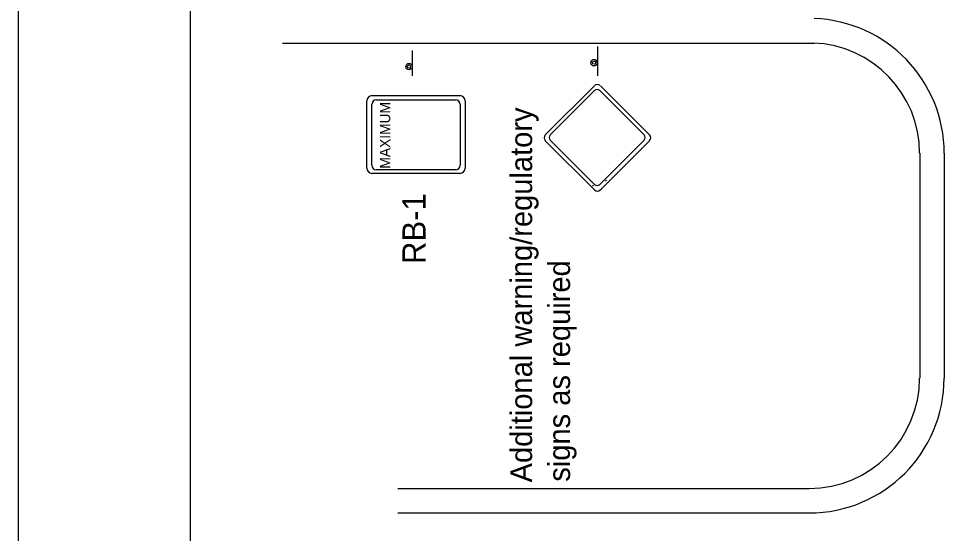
# Model space of a CAD drawing. Extents: x 2111 to 2327, y 208 to 487.
# Drawn here: x 2111.3 to 2214.3, y 349.6 to 406.9 of the extents above; entities that cross this region are included whole.
import ezdxf

# ---------------------------------------------------------------- set-up
doc = ezdxf.new("R2010")
doc.units = 0
for name, color, linetype in [('Level 10', 7, 'Continuous'), ('Level 2', 7, 'Continuous'), ('Level 44', 7, 'Continuous'), ('Level 60', 7, 'Continuous')]:
    doc.layers.add(name, color=color, linetype=linetype)

msp = doc.modelspace()

# ---------------------------------------------------------------- linework, layer by layer
at = {"layer": 'Level 10'}
for p, q in [((2140.66, 404.13), (2199.8, 404.13)), ((2211.55, 391.87), (2211.55, 366.86)), ((2214.27, 391.87), (2214.27, 366.86)), ((2153.49, 354.59), (2199.27, 354.59)), ((2153.49, 351.86), (2199.27, 351.86))]:
    msp.add_line(p, q, dxfattribs=at)
for centre, radius, start, end in [((2199.27, 391.87), 15, 0, 87.9751), ((2199.27, 391.87), 12.27, 0, 87.9751), ((2199.27, 366.86), 15, 270, 0), ((2199.27, 366.86), 12.27, 270, 0)]:
    msp.add_arc(centre, radius, start, end, dxfattribs=at)
at = {"layer": 'Level 2'}
for p, q in [((2175.26, 388.3), (2175.16, 388.2)), ((2175.26, 388.3), (2175.16, 388.2)), ((2176.72, 388.87), (2176.62, 388.76)), ((2176.72, 388.87), (2176.62, 388.76))]:
    msp.add_line(p, q, dxfattribs=at)
at = {"layer": 'Level 44'}
for p, q in [((2175.74, 400.49), (2175.74, 403.76)), ((2155.15, 400.49), (2155.15, 403.32)), ((2175.38, 399.39), (2169.9, 393.92)), ((2170.45, 393.92), (2175.38, 398.84)), ((2175.96, 398.84), (2180.89, 393.92)), ((2181.5, 393.92), (2176.03, 399.39)), ((2150.06, 390.2), (2150.06, 397.7)), ((2150.64, 398.28), (2160.41, 398.28)), ((2151.12, 397.8), (2159.92, 397.8)), ((2160.99, 397.7), (2160.99, 390.2)), ((2150.6, 390.53), (2150.6, 397.28)), ((2160.44, 397.28), (2160.44, 390.53)), ((2169.57, 393.6), (2169.57, 393.6)), ((2169.9, 393.27), (2175.38, 387.8)), ((2169.91, 393.27), (2169.9, 393.27)), ((2175.38, 388.41), (2170.45, 393.33)), ((2180.89, 393.33), (2175.96, 388.41)), ((2176.03, 387.8), (2181.5, 393.27)), ((2160.41, 389.63), (2150.64, 389.63)), ((2159.92, 390.01), (2151.12, 390.01)), ((2159.92, 390.01), (2159.92, 390.01)), ((2160.41, 389.63), (2160.41, 389.63))]:
    msp.add_line(p, q, dxfattribs=at)
for centre, radius in [((2154.75, 401.51), 0.363), ((2154.75, 401.51), 0.181), ((2175.33, 401.95), 0.363), ((2175.33, 401.95), 0.181)]:
    msp.add_circle(centre, radius, dxfattribs=at)
for centre, radius, start, end in [((2175.7, 399.07), 0.458, 45, 135), ((2175.67, 398.55), 0.412, 45, 135), ((2150.64, 397.7), 0.579, 90, 180), ((2151.12, 397.28), 0.521, 90, 180), ((2159.92, 397.28), 0.521, 360, 90), ((2160.41, 397.7), 0.579, 360, 90), ((2170.23, 393.6), 0.458, 135, 225), ((2170.74, 393.63), 0.412, 135, 225), ((2180.6, 393.63), 0.412, 315, 45), ((2181.18, 393.6), 0.458, 315, 45), ((2151.12, 390.53), 0.521, 180, 270), ((2159.92, 390.53), 0.521, 270, 360), ((2150.64, 390.21), 0.579, 180, 270), ((2160.41, 390.21), 0.579, 270, 360), ((2175.67, 388.7), 0.412, 225, 315), ((2175.7, 388.12), 0.458, 225, 315)]:
    msp.add_arc(centre, radius, start, end, dxfattribs=at)
at = {"layer": 'Level 60'}
for points in [[(2111.32, 487.21), (2327.32, 487.21), (2327.32, 208.21), (2111.32, 208.21)], [(2130.44, 476.4), (2317.32, 476.4), (2317.32, 219.02), (2130.44, 219.02)]]:
    msp.add_lwpolyline(points, close=True, dxfattribs=at)

# ---------------------------------------------------------------- texts
at = {"layer": 'Level 10'}
for s, height, p in [('Additional warning/regulatory', 2.419, (2168.44, 355.25)), ('RB-1', 2.585, (2156.6, 379.55)), ('signs as required', 2.419, (2172.66, 355.33))]:
    msp.add_text(s, height=height, rotation=90, dxfattribs=at).set_placement(p)
at = {"layer": 'Level 44'}
msp.add_text('MAXIMUM', height=1.147, rotation=90, dxfattribs=at).set_placement((2152.66, 390.16))

doc.saveas('drawing.dxf')
